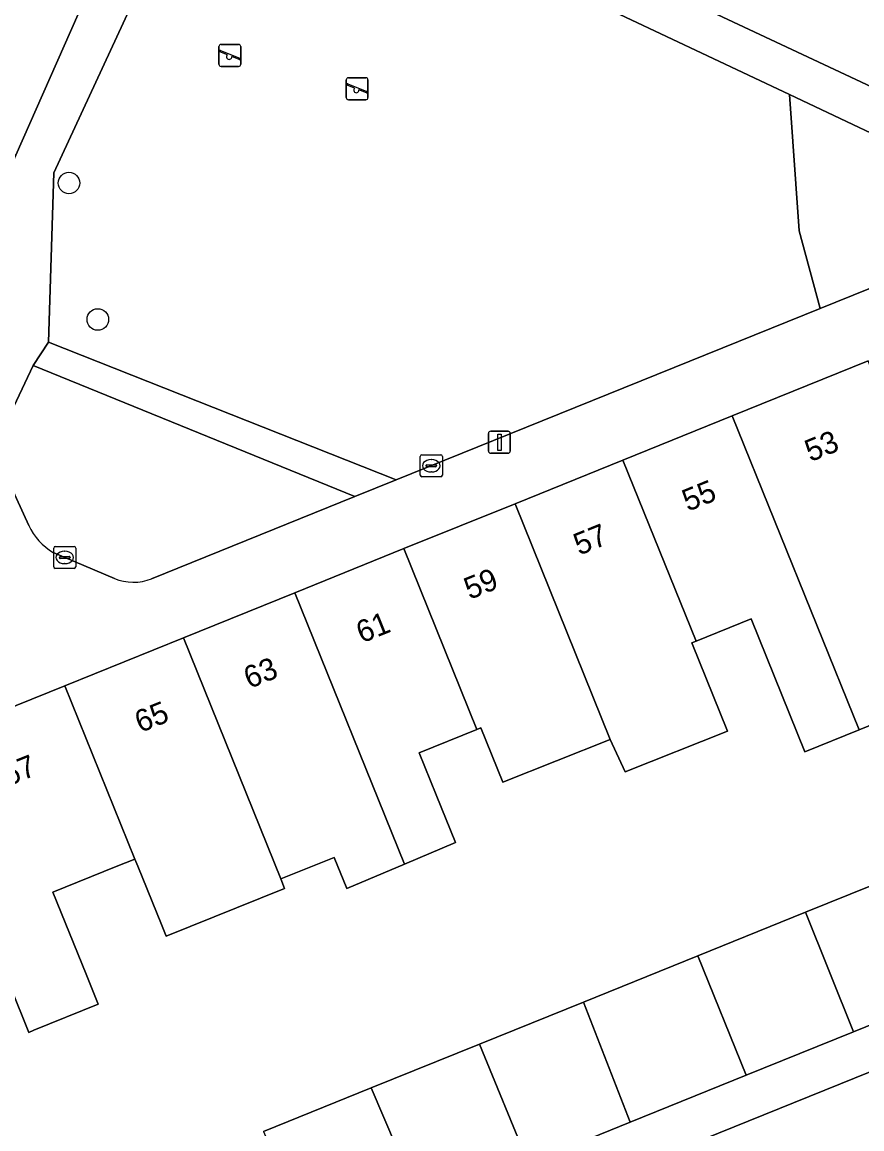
# Model space of a CAD drawing. Extents: x 162989 to 165008, y 383432 to 384338.
# Drawn here: x 163800.1 to 163838.2, y 383908.1 to 383958.3 of the extents above; entities that cross this region are included whole.
import ezdxf

# ---------------------------------------------------------------- set-up
doc = ezdxf.new("R2010")
doc.units = 0
for name, color, linetype in [('IMGEO_Boom', 7, 'Continuous'), ('IMGEO_Erf', 7, 'Continuous'), ('IMGEO_Groenvoorziening', 7, 'Continuous'), ('IMGEO_Kolk', 7, 'Continuous'), ('IMGEO_Lichtmast', 7, 'Continuous'), ('IMGEO_Pand', 7, 'Continuous'), ('IMGEO_Pand_nummerreeks', 7, 'Continuous'), ('IMGEO_Rijbaan_lokaal_open', 7, 'Continuous'), ('IMGEO_Speelvoorziening', 7, 'Continuous'), ('IMGEO_Voetpad_halfverhard', 7, 'Continuous'), ('IMGEO_Voetpad_open', 7, 'Continuous')]:
    doc.layers.add(name, color=color, linetype=linetype)

msp = doc.modelspace()

# ---------------------------------------------------------------- linework, layer by layer
at = {"layer": 'IMGEO_Boom'}
for centre in [(163802.218, 383951.041), (163803.526, 383944.847)]:
    msp.add_circle(centre, 0.489, dxfattribs=at)
at = {"layer": 'IMGEO_Erf'}
for points in [[(163840.633, 383927.235), (163838.098, 383926.211), (163835.631, 383925.215), (163833.194, 383931.246), (163830.698, 383930.237), (163830.499, 383930.157), (163832.115, 383926.159), (163827.475, 383924.308), (163826.8, 383925.781), (163821.922, 383923.835), (163820.923, 383926.305), (163820.741, 383926.231), (163818.12, 383925.172), (163818.894, 383923.256), (163819.769, 383921.091), (163817.456, 383920.115), (163814.837, 383919.009), (163814.266, 383920.422), (163811.845, 383919.443), (163812, 383919.008), (163806.629, 383916.838), (163806.413, 383917.372), (163805.34, 383920.027), (163805.212, 383920.345), (163804.359, 383920), (163801.487, 383918.84), (163802.991, 383915.121), (163803.543, 383913.753), (163800.625, 383912.572), (163800.392, 383912.477), (163798.718, 383916.612)], [(163811.057, 383907.981), (163815.946, 383909.958), (163820.853, 383911.942), (163825.576, 383913.852), (163830.772, 383915.953), (163835.659, 383917.929), (163840.73, 383919.98)]]:
    msp.add_lwpolyline(points, dxfattribs=at)
at = {"layer": 'IMGEO_Groenvoorziening'}
for points in [[(163804.047, 383974.212), (163794.914, 383954.592), (163799.81, 383952.313), (163803.556, 383960.811), (163802.806, 383961.228), (163805.552, 383967.331)], [(163805.971, 383933.075), (163815.199, 383936.805), (163800.585, 383942.761), (163798.804, 383939), (163799.522, 383937.418), (163800.395, 383935.495)], [(163801.507, 383934.26), (163804.28, 383933.092)]]:
    msp.add_lwpolyline(points, dxfattribs=at)
for points in [[(163842.634, 383958.132), (163811.375, 383972.879), (163809.621, 383969.034), (163840.864, 383954.38)], [(163836.33, 383945.345), (163835.381, 383948.865), (163834.933, 383955.059), (163808.865, 383967.368), (163801.532, 383951.511), (163801.292, 383943.817), (163817.081, 383937.565)], [(163843.038, 383948.056), (163841.53, 383951.944), (163834.933, 383955.059), (163835.381, 383948.865), (163836.33, 383945.345)]]:
    msp.add_lwpolyline(points, close=True, dxfattribs=at)
for centre, radius, start, end in [((163802.888, 383936.622), 2.736, 204.321, 239.6791), ((163805.146, 383935.121), 2.206, 246.8826, 291.9654)]:
    msp.add_arc(centre, radius, start, end, dxfattribs=at)
at = {"layer": 'IMGEO_Kolk'}
for p, q in [((163818.172, 383937.777), (163818.172, 383938.629)), ((163818.247, 383938.703), (163819.099, 383938.703)), ((163819.173, 383938.629), (163819.173, 383937.777)), ((163818.431, 383938.197), (163818.431, 383938.209)), ((163818.869, 383938.16), (163818.471, 383938.16)), ((163818.474, 383938.246), (163818.872, 383938.246)), ((163818.66, 383938.483), (163818.685, 383938.483)), ((163818.915, 383938.209), (163818.915, 383938.197)), ((163819.099, 383937.703), (163818.247, 383937.703)), ((163818.683, 383937.923), (163818.658, 383937.923)), ((163801.523, 383933.615), (163801.523, 383934.467)), ((163801.598, 383934.541), (163802.45, 383934.541)), ((163801.825, 383934.084), (163802.223, 383934.084)), ((163802.011, 383934.321), (163802.036, 383934.321)), ((163802.524, 383934.467), (163802.524, 383933.615)), ((163801.782, 383934.035), (163801.782, 383934.047)), ((163802.22, 383933.998), (163801.822, 383933.998)), ((163802.034, 383933.761), (163802.009, 383933.761)), ((163802.266, 383934.047), (163802.266, 383934.035)), ((163802.45, 383933.541), (163801.598, 383933.541))]:
    msp.add_line(p, q, dxfattribs=at)
for points in [[(163818.172, 383937.777), (163818.172, 383938.629)], [(163818.247, 383938.703), (163819.099, 383938.703)], [(163819.173, 383938.629), (163819.173, 383937.777)], [(163819.099, 383937.703), (163818.247, 383937.703)], [(163801.523, 383933.615), (163801.523, 383934.467)], [(163801.598, 383934.541), (163802.45, 383934.541)], [(163802.524, 383934.467), (163802.524, 383933.615)], [(163802.45, 383933.541), (163801.598, 383933.541)]]:
    msp.add_lwpolyline(points, dxfattribs=at)
for centre, radius, start, end in [((163818.249, 383938.627), 0.0765, 91.552, 178.448), ((163818.249, 383938.627), 0.0765, 91.552, 178.448), ((163819.097, 383938.627), 0.0765, 1.552, 88.448), ((163819.097, 383938.627), 0.0765, 1.552, 88.448), ((163818.471, 383938.206), 0.0403, 85.8775, 175.7526), ((163818.468, 383938.196), 0.0366, 178.938, 274.7102), ((163818.872, 383938.203), 0.043, 264.8664, 352.4533), ((163818.876, 383938.208), 0.0386, 1.7309, 96.639), ((163818.249, 383937.779), 0.0765, 181.552, 268.448), ((163818.249, 383937.779), 0.0765, 181.552, 268.448), ((163819.097, 383937.779), 0.0765, 271.552, 358.448), ((163819.097, 383937.779), 0.0765, 271.552, 358.448), ((163801.6, 383934.465), 0.0765, 91.552, 178.448), ((163801.6, 383934.465), 0.0765, 91.552, 178.448), ((163801.822, 383934.044), 0.0403, 85.8775, 175.7526), ((163802.227, 383934.046), 0.0386, 1.7309, 96.639), ((163802.448, 383934.465), 0.0765, 1.552, 88.448), ((163802.448, 383934.465), 0.0765, 1.552, 88.448), ((163801.6, 383933.617), 0.0765, 181.552, 268.448), ((163801.6, 383933.617), 0.0765, 181.552, 268.448), ((163801.819, 383934.034), 0.0366, 178.938, 274.7102), ((163802.223, 383934.041), 0.043, 264.8664, 352.4533), ((163802.448, 383933.617), 0.0765, 271.552, 358.448), ((163802.448, 383933.617), 0.0765, 271.552, 358.448)]:
    msp.add_arc(centre, radius, start, end, dxfattribs=at)
for centre, major_axis, ratio, start_param, end_param in [((163818.659, 383938.203), (-0.387, 0.002), 0.722429, 4.712389, 7.853982), ((163818.684, 383938.203), (-0.39, 0.002), 0.717154, 1.570796, 4.712389), ((163802.01, 383934.041), (-0.387, 0.002), 0.722429, 4.712389, 7.853982), ((163802.035, 383934.041), (-0.39, 0.002), 0.717154, 1.570796, 4.712389)]:
    msp.add_ellipse(centre, major_axis=major_axis, ratio=ratio, start_param=start_param, end_param=end_param, dxfattribs=at)
at = {"layer": 'IMGEO_Lichtmast'}
for p, q in [((163821.268, 383938.87), (163821.268, 383939.67)), ((163821.268, 383939.67), (163821.268, 383938.87)), ((163821.368, 383939.77), (163822.158, 383939.77)), ((163822.158, 383939.77), (163821.368, 383939.77)), ((163822.258, 383939.67), (163822.258, 383938.87)), ((163822.258, 383938.87), (163822.258, 383939.67)), ((163822.158, 383938.77), (163821.368, 383938.77)), ((163821.368, 383938.77), (163822.158, 383938.77))]:
    msp.add_line(p, q, dxfattribs=at)
msp.add_lwpolyline([(163821.688, 383939.645), (163821.838, 383939.645), (163821.838, 383938.895), (163821.688, 383938.895), (163821.688, 383939.645)], dxfattribs=at)
for centre, start, end in [((163821.368, 383939.67), 90, 180), ((163821.368, 383939.67), 90, 180), ((163822.158, 383939.67), 0, 90), ((163822.158, 383939.67), 360, 90), ((163821.368, 383938.87), 180, 270), ((163821.368, 383938.87), 180, 270), ((163822.158, 383938.87), 270, 0), ((163822.158, 383938.87), 270, 0)]:
    msp.add_arc(centre, 0.1, start, end, dxfattribs=at)
at = {"layer": 'IMGEO_Pand'}
for points in [[(163841.841, 383934.731), (163838.514, 383942.964), (163832.336, 383940.467), (163838.098, 383926.211), (163840.633, 383927.235), (163839.142, 383930.925), (163841.827, 383932.01), (163840.884, 383934.344)], [(163838.098, 383926.211), (163832.336, 383940.467), (163827.375, 383938.462), (163830.698, 383930.237), (163833.194, 383931.246), (163835.631, 383925.215)], [(163827.375, 383938.462), (163822.475, 383936.481), (163826.8, 383925.781), (163827.475, 383924.308), (163832.115, 383926.159), (163830.499, 383930.157), (163830.698, 383930.237)], [(163820.741, 383926.231), (163820.923, 383926.305), (163821.922, 383923.835), (163826.8, 383925.781), (163822.475, 383936.481), (163817.424, 383934.44)], [(163820.741, 383926.231), (163817.424, 383934.44), (163812.474, 383932.44), (163817.456, 383920.115), (163819.769, 383921.091), (163818.894, 383923.256), (163818.12, 383925.172)], [(163811.845, 383919.443), (163814.266, 383920.422), (163814.837, 383919.009), (163817.456, 383920.115), (163812.474, 383932.44), (163807.418, 383930.396)], [(163807.418, 383930.396), (163802.029, 383928.218), (163805.212, 383920.345), (163805.34, 383920.027), (163806.413, 383917.372), (163806.629, 383916.838), (163812, 383919.008), (163811.845, 383919.443)], [(163802.029, 383928.218), (163795.378, 383925.53), (163795.145, 383925.436), (163798.718, 383916.612), (163800.392, 383912.477), (163800.625, 383912.572), (163803.543, 383913.753), (163802.991, 383915.121), (163801.487, 383918.84), (163804.359, 383920), (163805.212, 383920.345)], [(163835.659, 383917.929), (163837.847, 383912.5), (163842.965, 383914.57), (163840.73, 383919.98)], [(163830.772, 383915.953), (163832.966, 383910.526), (163837.847, 383912.5), (163835.659, 383917.929)], [(163827.707, 383908.399), (163832.966, 383910.526), (163830.772, 383915.953), (163825.576, 383913.852)], [(163827.707, 383908.399), (163825.576, 383913.852), (163820.853, 383911.942), (163823.081, 383906.528)], [(163815.946, 383909.958), (163818.239, 383904.57), (163823.081, 383906.528), (163820.853, 383911.942)], [(163815.946, 383909.958), (163811.057, 383907.981), (163813.375, 383902.603), (163818.239, 383904.57)]]:
    msp.add_lwpolyline(points, close=True, dxfattribs=at)
at = {"layer": 'IMGEO_Rijbaan_lokaal_open'}
msp.add_lwpolyline([(163871.097, 383919.517), (163872.52, 383920.092), (163871.094, 383923.633), (163869.631, 383923.057), (163864.475, 383921.044), (163862.45, 383920.253), (163860.077, 383919.099), (163859.978, 383919.33), (163805.517, 383897.306), (163806.86, 383893.986), (163806.955, 383893.639), (163833.434, 383904.225)], dxfattribs=at)
at = {"layer": 'IMGEO_Speelvoorziening'}
for p, q in [((163809.029, 383956.438), (163809.029, 383957.238)), ((163809.029, 383957.238), (163809.029, 383956.438)), ((163809.129, 383957.338), (163809.919, 383957.338)), ((163809.919, 383957.338), (163809.129, 383957.338)), ((163810.019, 383957.238), (163810.019, 383956.438)), ((163810.019, 383956.438), (163810.019, 383957.238)), ((163809.412, 383956.866), (163809.073, 383957.003)), ((163809.098, 383957.063), (163809.974, 383956.71)), ((163809.95, 383956.65), (163809.61, 383956.787)), ((163809.919, 383956.338), (163809.129, 383956.338)), ((163809.129, 383956.338), (163809.919, 383956.338)), ((163814.806, 383954.923), (163814.806, 383955.723)), ((163814.806, 383955.723), (163814.806, 383954.923)), ((163814.906, 383955.823), (163815.696, 383955.823)), ((163815.696, 383955.823), (163814.906, 383955.823)), ((163815.796, 383955.723), (163815.796, 383954.923)), ((163815.796, 383954.923), (163815.796, 383955.723)), ((163815.189, 383955.351), (163814.85, 383955.488)), ((163814.875, 383955.548), (163815.751, 383955.195)), ((163815.727, 383955.135), (163815.387, 383955.272)), ((163815.696, 383954.823), (163814.906, 383954.823)), ((163814.906, 383954.823), (163815.696, 383954.823))]:
    msp.add_line(p, q, dxfattribs=at)
for centre, radius, start, end in [((163809.129, 383957.238), 0.1, 90, 180), ((163809.129, 383957.238), 0.1, 90, 180), ((163809.919, 383957.238), 0.1, 0, 90), ((163809.919, 383957.238), 0.1, 360, 90), ((163809.086, 383957.033), 0.0327, 68.078, 248.078), ((163809.491, 383956.776), 0.12, 130.9928, 5.1632), ((163809.962, 383956.68), 0.0327, 248.078, 68.078), ((163809.129, 383956.438), 0.1, 180, 270), ((163809.129, 383956.438), 0.1, 180, 270), ((163809.919, 383956.438), 0.1, 270, 0), ((163809.919, 383956.438), 0.1, 270, 0), ((163814.906, 383955.723), 0.1, 90, 180), ((163814.906, 383955.723), 0.1, 90, 180), ((163815.696, 383955.723), 0.1, 0, 90), ((163815.696, 383955.723), 0.1, 360, 90), ((163814.863, 383955.518), 0.0327, 68.078, 248.078), ((163815.268, 383955.261), 0.12, 130.9928, 5.1632), ((163815.739, 383955.165), 0.0327, 248.078, 68.078), ((163814.906, 383954.923), 0.1, 180, 270), ((163814.906, 383954.923), 0.1, 180, 270), ((163815.696, 383954.923), 0.1, 270, 0), ((163815.696, 383954.923), 0.1, 270, 0)]:
    msp.add_arc(centre, radius, start, end, dxfattribs=at)
at = {"layer": 'IMGEO_Voetpad_halfverhard'}
for points in [[(163808.865, 383967.368), (163809.621, 383969.034), (163811.375, 383972.879), (163809.387, 383973.817), (163806.315, 383966.966), (163805.552, 383967.331), (163802.806, 383961.228), (163803.556, 383960.811), (163799.81, 383952.313), (163799.689, 383952.038), (163799.549, 383944.941), (163797.807, 383941.195), (163798.804, 383939), (163800.585, 383942.761), (163801.292, 383943.817), (163801.532, 383951.511)], [(163809.621, 383969.034), (163808.865, 383967.368), (163834.933, 383955.059), (163841.53, 383951.944), (163842.921, 383953.612), (163844.681, 383957.165), (163842.634, 383958.132), (163840.864, 383954.38)], [(163801.292, 383943.817), (163800.585, 383942.761), (163815.199, 383936.805), (163817.081, 383937.565)]]:
    msp.add_lwpolyline(points, close=True, dxfattribs=at)
at = {"layer": 'IMGEO_Voetpad_open'}
for points in [[(163852.603, 383952.214), (163849.565, 383950.694), (163844.704, 383948.729), (163843.038, 383948.056), (163836.33, 383945.345), (163817.081, 383937.565), (163815.199, 383936.805), (163805.971, 383933.075)], [(163800.395, 383935.495), (163799.522, 383937.418), (163793.673, 383924.841), (163795.145, 383925.436), (163795.378, 383925.53), (163802.029, 383928.218), (163807.418, 383930.396), (163812.474, 383932.44), (163817.424, 383934.44), (163822.475, 383936.481), (163827.375, 383938.462), (163832.336, 383940.467), (163838.514, 383942.964)], [(163804.28, 383933.092), (163801.507, 383934.26)]]:
    msp.add_lwpolyline(points, dxfattribs=at)
msp.add_lwpolyline([(163859.978, 383919.33), (163859.203, 383921.136), (163859.018, 383921.061), (163854.065, 383919.058), (163848.956, 383916.992), (163842.965, 383914.57), (163837.847, 383912.5), (163832.966, 383910.526), (163827.707, 383908.399), (163823.081, 383906.528), (163818.239, 383904.57), (163813.375, 383902.603), (163806.022, 383899.63), (163804.877, 383898.889), (163805.517, 383897.306)], close=True, dxfattribs=at)
for centre, radius, start, end in [((163802.888, 383936.622), 2.736, 204.321, 239.6791), ((163805.146, 383935.121), 2.206, 246.8826, 291.9654)]:
    msp.add_arc(centre, radius, start, end, dxfattribs=at)

# ---------------------------------------------------------------- texts
at = {"layer": 'IMGEO_Pand_nummerreeks'}
for s, rotation, p in [('53', 22.0073, (163835.888, 383938.365)), ('55', 22.0152, (163830.319, 383936.113)), ('57', 22.0027, (163825.387, 383934.12)), ('59', 22.0014, (163820.412, 383932.11)), ('61', 22.0064, (163815.517, 383930.131)), ('63', 22.0064, (163810.409, 383928.067)), ('65', 22.0073, (163805.46, 383926.067)), ('67', 22.0073, (163799.44, 383923.634))]:
    msp.add_text(s, height=1, rotation=rotation, dxfattribs=at).set_placement(p)

doc.saveas('drawing.dxf')
